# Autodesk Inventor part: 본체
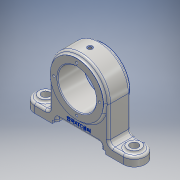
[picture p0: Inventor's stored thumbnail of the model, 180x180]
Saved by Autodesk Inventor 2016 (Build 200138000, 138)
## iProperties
Created: 2019-05
Part Number: 본체
Material: 알루미늄 6061
Document SubType Name: Modeling
Designer: USER
Density: 2.7 g/cm^3
Appearance: 알루미늄 - 평지
Mass: 455.027 g
Surface Area: 318.707 cm^2
Volume: 168.528 cm^3
Author: USER
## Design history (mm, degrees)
sketch "스케치1"
  geometry: L1 (40, 0)-(40, -48); L2 (40, -48)-(60, -48); L3 (60, -48)-(60, -60); L4 (60, -60)-(36, -60); L5 (36, -60)-(36, -56); L6 (36, -56)-(30, -56); L7 (30, -56)-(30, -50); L8 (30, -50)-(20.377, -50); L9 (0, 0)-(0, -81.993); L10 (-40, 0)-(-40, -48); L11 (-40, -48)-(-60, -48); L12 (-60, -48)-(-60, -60); L13 (-36, -60)-(-36, -56); L14 (-36, -56)-(-30, -56); L15 (-30, -56)-(-30, -50); L16 (-30, -50)-(20.377, -50); L17 (-60, -60)-(-36, -60); A1 r 40 centre (0, 0) between (40, 0) and (-40, 0); 1 further point
  constraints: 34 end point, 8 symmetric about line, 7 perpendicular, 2 point on circle, 2 vertical, 1 centre point, 1 coincident, 1 tangent
  dimensions: "d0" = 80 diameter of A1; "d1" = 60 distance from line of L17 point (0, 0); "d2" = 72 distance between parallel lines of L13 L5; "d3" = 60 distance between parallel lines of L15 L7; "d4" = 10 distance between parallel lines of L4 L16; "d5" = 4 distance between parallel lines of L4 L6; "d6" = 12 distance between parallel lines of L4 L2; "d7" = 120 distance between parallel lines of L3 L12
extrude "돌출1" new body sketch "스케치1" stored distance "d9" = 30; taper "d10" = 0 deg
sketch "스케치2"
  geometry: L1 (20, -30)-(20, 0) reference; L2 (-100, -30)-(-100, 0) reference; L3 (-76, 0)-(-100, 0) reference; 3 further points
  constraints: 2 midpoint, 2 vertical alignment, 4 other
extrude "돌출2" join sketch "스케치2" distance "d11" = 12; taper "d12" = 0 deg
sketch "스케치3"
  geometry: C1 r 9 at (20, 15); C2 r 9 at (-100, 15); A1 r 15 centre (20, 15) between (20, 0) and (20, 30) reference; A2 r 15 centre (-100, 15) between (-100, 30) and (-100, 0) reference; 1 further point
  constraints: 2 centre point, 2 coincident
  dimensions: "d13" = 18 diameter of C1; "d14" = 18 diameter of C2
extrude "돌출3" join sketch "스케치3" distance "d15" = 3; taper "d16" = 0 deg
sketch "스케치4"
  geometry: C1 r 9 at (0, 0) reference; C2 r 5.5 at (0, 0); 1 further point
  constraints: 1 centre point, 1 coincident
  dimensions: "d17" = 11 diameter of C2
extrude "돌출4" cut sketch "스케치4" stored distance "d18" = 3; taper "d19" = 0 deg
sketch "스케치5"
  geometry: C1 r 36 at (0, 0); 1 further point
  constraints: 1 centre point, 1 coincident
  dimensions: "d20" = 72 diameter of C1
extrude "돌출5" join sketch "스케치5" distance "d21" = 3; taper "d22" = 0 deg
sketch "스케치6"
  geometry: C1 r 26 at (0, 0); 1 further point
  constraints: 1 centre point, 1 coincident
  dimensions: "d23" = 52 diameter of C1
extrude "돌출6" cut sketch "스케치6" stored distance "d24" = 3; taper "d25" = 0 deg
node "작업 평면1"
sketch "스케치8"
  geometry: 2 further points
  constraints: 1 coincident
hole "구멍1" sketch "스케치8" at (0, 0) diameter "d30" = 4.917; stored, may be unused: countersink angle "d34" = 90 deg, drill point angle "d36" = 118 deg; dims "d31" = 8, "d32" = 7, "d33" = 1, "d35" = 10
sketch "스케치9"
  geometry: C1 r 1 at (0, 0); 1 further point
  constraints: 1 centre point, 1 coincident
  dimensions: "d37" = 2 diameter of C1
extrude "돌출8" cut sketch "스케치9" stored distance "d38" = 3; taper "d39" = 0 deg
sketch "스케치10"
  geometry: L1 (0, 0)-(0, 26); C1 r 1.5 at (0, 26); 1 further point
  constraints: 2 end point, 1 centre point, 1 coincident, 1 vertical, 1 vertical alignment, 1 other
  dimensions: "d40" = 3 diameter of C1
extrude "돌출9" cut sketch "스케치10" stored distance "d41" = 3; taper "d42" = 0 deg
sketch "스케치11"
  geometry: L1 (0, 0)-(0, 31); 1 further point
  constraints: 2 end point, 1 coincident, 1 vertical
  dimensions: "d43" = 31 distance of L1.start L1.end
hole "구멍2" sketch "스케치11" at (0, 31) diameter "d44" = 3.242; stored, may be unused: countersink angle "d48" = 90 deg, drill point angle "d50" = 118 deg; dims "d45" = 6, "d46" = 7, "d47" = 1, "d49" = 8
fillet "모깎기1" dims "d54" = 6
fillet "모깎기2" dims "d55" = 3
chamfer "모따기1" distance "d56" = 1; stored, may be unused: second distance "d57" = 2, angle "d58" = 45 deg
sketch "스케치12"
  geometry: L1 (0, 0)-(0, -50); L2 (27, -50)-(-27, -50) reference; 1 further point
  constraints: 2 end point, 1 midpoint, 1 point on line, 1 other
  dimensions: "d59" = 7 distance from line of point (0, -43) L2
feature "엠보싱1" sketch "스케치12" dims "d0" = 80, "d1" = 60, "d2" = 72, "d3" = 60, "d4" = 10, "d5" = 4, "d6" = 12, "d7" = 120, "d60" = 0.5, "d61" = 0
node "솔리드1"
mirror "대칭1"
mirror "대칭2"
pattern_circular "원형 패턴1" dims angle "d52" = 360 deg
mirror "대칭3"
